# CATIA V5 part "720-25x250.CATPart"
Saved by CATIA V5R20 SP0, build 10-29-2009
Part number: 720-25x250
Definition: NONE
Nomenclature: 720-25x250
Source: Unknown
Description: 720-25x250
Bounding box of the stored display mesh (mm): x 0 to 250, y -12.5 to 12.5, z -12.5 to 12.5
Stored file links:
  C:\Users\Utente\Desktop\IO LAVORO\3D X SITO CF\X SITO\720\720-25x250.CATPart
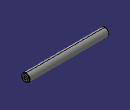
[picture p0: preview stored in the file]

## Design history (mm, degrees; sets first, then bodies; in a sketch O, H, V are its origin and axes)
Body1 "720-25x250" (main body)
  Solid1: solid without history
